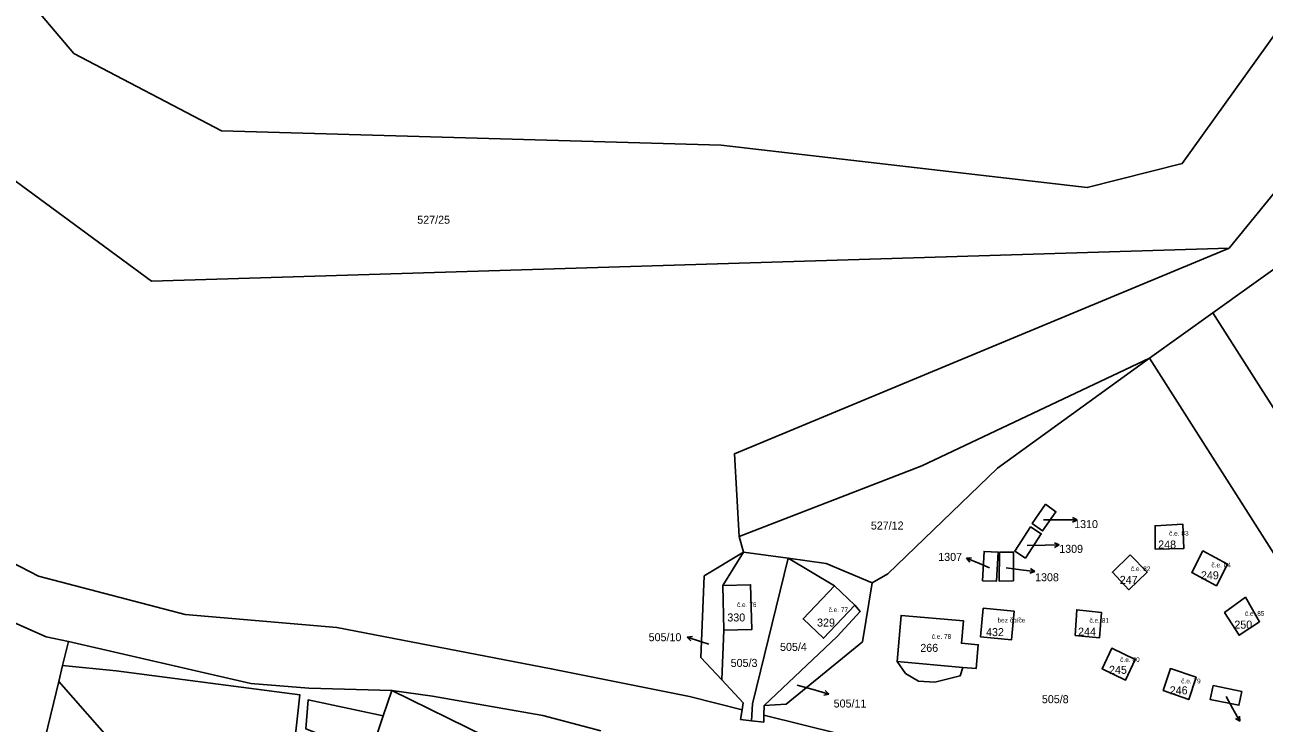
# Model space of a CAD drawing. Extents: x -887272 to -880188, y -1026687 to -1021896.
# Drawn here: x -883908.9 to -883645.6, y -1024025.9 to -1023877.6 of the extents above; entities that cross this region are included whole.
import ezdxf

# ---------------------------------------------------------------- set-up
doc = ezdxf.new("R2010")
doc.units = 0
for name, color, linetype in [('Definiční body', 7, 'Continuous'), ('Hranice parcel', 7, 'Continuous'), ('Parcelní čísla', 7, 'Continuous'), ('Polygon budovy', 7, 'Continuous'), ('Pop  PČ popisy', 7, 'Continuous'), ('Vnitřní kresba', 7, 'Continuous')]:
    doc.layers.add(name, color=color, linetype=linetype)

msp = doc.modelspace()

# ---------------------------------------------------------------- linework, layer by layer
at = {"layer": 'Hranice parcel'}
for p, q in [((-883618.89, -1023883.14), (-883653, -1023925)), ((-883656.45, -1023938.75), (-883630.8, -1023920.38)), ((-883656.45, -1023938.75), (-883669.93, -1023948.4)), ((-883590.41, -1024042.65), (-883656.45, -1023938.75)), ((-883608.39, -1024045.1), (-883669.93, -1023948.4)), ((-883757.1, -1023986.22), (-883756.18, -1023989.56)), ((-883756.18, -1023989.56), (-883760.62, -1023996.66)), ((-883746.68, -1023990.84), (-883756.18, -1023989.56)), ((-883736.89, -1023996.69), (-883746.68, -1023990.84)), ((-883760.62, -1023996.66), (-883760.36, -1024006.16)), ((-883732.53, -1024000.81), (-883736.89, -1023996.69)), ((-883705.25, -1024001.45), (-883705.83, -1024007.56)), ((-883760.36, -1024006.16), (-883760.82, -1024016.71)), ((-883899.62, -1024008.57), (-883900.86, -1024013.67)), ((-883900.86, -1024013.67), (-883901.68, -1024017.03)), ((-883904.58, -1024028.99), (-883901.68, -1024017.03)), ((-883751.78, -1024022.1), (-883751.85, -1024024.16)), ((-883832.76, -1024024.32), (-883835.54, -1024032.54))]:
    msp.add_line(p, q, dxfattribs=at)
for points in [[(-883756.5, -1024023.04), (-883767.66, -1024020.24), (-883797.06, -1024014.34), (-883842.62, -1024005.56), (-883874.8, -1024002.84), (-883906.02, -1023994.68), (-883929.04, -1023982.78), (-884005.12, -1023932.5), (-884033.98, -1023912.56), (-884080.28, -1023877.34), (-884136.58, -1023830.48), (-884162.3, -1023804.42), (-884180.14, -1023781.6), (-884204.86, -1023736.02), (-884224.62, -1023704.92), (-884247.24, -1023674.52), (-884253.66, -1023666.34), (-884254.22, -1023665.64)], [(-883940.39, -1023824.94), (-883938.55, -1023836.46), (-883898.48, -1023883.66), (-883867.13, -1023900.11), (-883760.97, -1023903.17), (-883683.16, -1023912.16), (-883662.96, -1023907.05), (-883633.66, -1023866.14)], [(-883979.65, -1023860.19), (-883882, -1023932), (-883653, -1023925)], [(-883653, -1023925), (-883758.14, -1023968.71), (-883757.1, -1023986.22)], [(-883757.1, -1023986.22), (-883718.33, -1023971.26), (-883669.93, -1023948.4)], [(-883669.93, -1023948.4), (-883702.2, -1023971.74), (-883725.5, -1023994.16), (-883728.86, -1023996.08)], [(-883692.06, -1023979.41), (-883689.83, -1023980.99), (-883692.66, -1023985.08), (-883694.85, -1023983.5), (-883692.06, -1023979.41)], [(-883696.29, -1023990.83), (-883698.57, -1023989.35), (-883695.21, -1023984.2), (-883692.94, -1023985.66), (-883696.29, -1023990.83)], [(-883668.72, -1023988.96), (-883662.66, -1023988.8), (-883662.82, -1023983.66), (-883668.76, -1023983.98), (-883668.72, -1023988.96)], [(-883756.18, -1023989.56), (-883764.52, -1023994.6), (-883765.26, -1024011.96), (-883760.82, -1024016.71)], [(-883705.41, -1023995.64), (-883705.06, -1023989.43), (-883702.05, -1023989.57), (-883702.41, -1023995.71), (-883705.41, -1023995.64)], [(-883698.81, -1023995.68), (-883701.86, -1023995.72), (-883701.8, -1023989.58), (-883698.81, -1023989.56), (-883698.81, -1023995.68)], [(-883674.06, -1023990.16), (-883677.82, -1023993.84), (-883674.3, -1023997.54), (-883670.42, -1023993.82), (-883674.06, -1023990.16)], [(-883660.94, -1023993.92), (-883655.72, -1023996.7), (-883653.38, -1023992.12), (-883658.58, -1023989.3), (-883660.94, -1023993.92)], [(-883754.5, -1024025.36), (-883754.29, -1024021.81), (-883746.68, -1023990.84)], [(-883746.68, -1023990.84), (-883738.64, -1023991.96), (-883728.86, -1023996.08)], [(-883760.36, -1024006.16), (-883754.46, -1024006), (-883754.7, -1023996.5), (-883760.62, -1023996.66)], [(-883728.86, -1023996.08), (-883730.9, -1024008.58), (-883747.14, -1024021.86), (-883751.78, -1024022.1)], [(-883736.89, -1023996.69), (-883743.54, -1024003.74), (-883739.18, -1024007.85), (-883732.53, -1024000.81)], [(-883751.78, -1024022.1), (-883736.3, -1024007.5), (-883731.4, -1024002.14), (-883732.53, -1024000.81)], [(-883646.54, -1024004.34), (-883649.54, -1023999.13), (-883653.96, -1024002.38), (-883650.88, -1024007.22), (-883646.54, -1024004.34)], [(-883913.13, -1024003.65), (-883904.38, -1024007.55), (-883899.62, -1024008.57)], [(-883706.76, -1024014.3), (-883706.31, -1024009.22), (-883709.9, -1024008.9), (-883709.48, -1024004.13), (-883722.73, -1024003.02), (-883723.54, -1024012.82)], [(-883705.83, -1024007.56), (-883699.25, -1024008.18), (-883698.7, -1024002.1), (-883705.25, -1024001.45)], [(-883680.54, -1024007.74), (-883680.16, -1024002.36), (-883685.4, -1024001.8), (-883685.72, -1024007.26), (-883680.54, -1024007.74)], [(-883899.62, -1024008.57), (-883860.9, -1024017.44), (-883848.52, -1024018.46), (-883830.95, -1024018.96), (-883822.3, -1024020.14), (-883798.84, -1024024.24), (-883786.49, -1024027.54)], [(-883675.06, -1024016.78), (-883672.96, -1024012.34), (-883677.96, -1024009.96), (-883680, -1024014.34), (-883675.06, -1024016.78)], [(-883867.76, -1024045.3), (-883853.82, -1024050.22), (-883850.5, -1024019.86), (-883889.5, -1024014.8), (-883900.86, -1024013.67)], [(-883723.54, -1024012.82), (-883721.76, -1024015.36), (-883719, -1024016.96), (-883715.56, -1024017.2), (-883710.18, -1024015.86), (-883709.57, -1024014.05), (-883706.76, -1024014.3)], [(-883661.58, -1024020.86), (-883660.02, -1024016.12), (-883665.48, -1024014.3), (-883667.02, -1024018.94), (-883661.58, -1024020.86)], [(-883901.68, -1024017.03), (-883886.96, -1024033.84), (-883874.14, -1024042.96), (-883867.76, -1024045.3)], [(-883760.82, -1024016.71), (-883756.28, -1024021.58), (-883756.5, -1024023.04)], [(-883835.54, -1024032.54), (-883818.36, -1024041.34), (-883811, -1024028.73), (-883830.95, -1024018.96), (-883832.76, -1024024.32)], [(-883650.34, -1024019.14), (-883650.92, -1024022.08), (-883657.05, -1024020.84), (-883656.37, -1024017.92), (-883650.34, -1024019.14)], [(-883832.76, -1024024.32), (-883848.72, -1024020.95), (-883849.18, -1024027.12), (-883835.54, -1024032.54)], [(-883756.5, -1024023.04), (-883756.81, -1024025.08), (-883754.5, -1024025.36)], [(-883751.85, -1024024.16), (-883751.9, -1024025.67), (-883754.5, -1024025.36)], [(-883751.85, -1024024.16), (-883686.7, -1024040.32), (-883639.5, -1024046.16), (-883608.39, -1024045.1)]]:
    msp.add_lwpolyline(points, dxfattribs=at)
at = {"layer": 'Polygon budovy'}
for points in [[(-883668.76, -1023983.98), (-883668.72, -1023988.96), (-883662.66, -1023988.8), (-883662.82, -1023983.66)], [(-883674.06, -1023990.16), (-883677.82, -1023993.84), (-883674.3, -1023997.54), (-883670.42, -1023993.82)], [(-883658.58, -1023989.3), (-883660.94, -1023993.92), (-883655.72, -1023996.7), (-883653.38, -1023992.12)], [(-883760.36, -1024006.16), (-883754.46, -1024006), (-883754.7, -1023996.5), (-883760.62, -1023996.66)], [(-883743.54, -1024003.74), (-883739.18, -1024007.85), (-883732.53, -1024000.81), (-883736.89, -1023996.69)], [(-883653.96, -1024002.38), (-883650.88, -1024007.22), (-883646.54, -1024004.34), (-883649.54, -1023999.13)], [(-883722.73, -1024003.02), (-883723.54, -1024012.82), (-883709.57, -1024014.05), (-883706.76, -1024014.3), (-883706.31, -1024009.22), (-883709.9, -1024008.9), (-883709.48, -1024004.13)], [(-883705.25, -1024001.45), (-883705.83, -1024007.56), (-883699.25, -1024008.18), (-883698.7, -1024002.1)], [(-883685.4, -1024001.8), (-883685.72, -1024007.26), (-883680.54, -1024007.74), (-883680.16, -1024002.36)], [(-883672.96, -1024012.34), (-883677.96, -1024009.96), (-883680, -1024014.34), (-883675.06, -1024016.78)], [(-883665.48, -1024014.3), (-883667.02, -1024018.94), (-883661.58, -1024020.86), (-883660.02, -1024016.12)]]:
    msp.add_lwpolyline(points, close=True, dxfattribs=at)
at = {"layer": 'Pop  PČ popisy'}
for p, q in [((-883692.48, -1023982.69), (-883688.29, -1023982.71)), ((-883688.29, -1023982.71), (-883685.29, -1023982.71)), ((-883685.29, -1023982.71), (-883686.29, -1023982.21)), ((-883685.29, -1023982.71), (-883686.29, -1023983.21)), ((-883692.1, -1023988.1), (-883689.1, -1023988.05)), ((-883689.1, -1023988.05), (-883690.11, -1023987.56)), ((-883689.1, -1023988.05), (-883690.09, -1023988.57)), ((-883695.94, -1023988.16), (-883692.1, -1023988.1)), ((-883708.83, -1023990.87), (-883707.72, -1023990.78)), ((-883706.05, -1023991.99), (-883708.83, -1023990.87)), ((-883708.83, -1023990.87), (-883708.09, -1023991.71)), ((-883703.9, -1023992.87), (-883706.05, -1023991.99)), ((-883700.37, -1023992.93), (-883697.25, -1023993.3)), ((-883697.25, -1023993.3), (-883694.27, -1023993.67)), ((-883694.27, -1023993.67), (-883695.2, -1023993.05)), ((-883694.27, -1023993.67), (-883695.33, -1023994.04)), ((-883768.15, -1024007.63), (-883767.05, -1024007.47)), ((-883765.3, -1024008.56), (-883768.15, -1024007.63)), ((-883768.15, -1024007.63), (-883767.36, -1024008.42)), ((-883763.59, -1024009.12), (-883765.3, -1024008.56)), ((-883744.78, -1024017.82), (-883740.93, -1024018.9)), ((-883740.93, -1024018.9), (-883738.05, -1024019.73)), ((-883738.05, -1024019.73), (-883738.87, -1024018.97)), ((-883738.05, -1024019.73), (-883739.15, -1024019.93)), ((-883653.67, -1024020.23), (-883652.2, -1024022.87)), ((-883652.2, -1024022.87), (-883650.74, -1024025.49)), ((-883650.74, -1024025.49), (-883651.67, -1024024.86)), ((-883650.74, -1024025.49), (-883650.79, -1024024.38))]:
    msp.add_line(p, q, dxfattribs=at)
at = {"layer": 'Vnitřní kresba'}
msp.add_line((-883723.54, -1024012.82), (-883709.57, -1024014.05), dxfattribs=at)

# ---------------------------------------------------------------- texts
at = {"layer": 'Definiční body'}
for s, p in [('č.e. 83', (-883665.77, -1023986.07)), ('č.e. 82', (-883673.88, -1023993.59)), ('č.e. 84', (-883656.77, -1023992.8)), ('č.e. 76', (-883757.59, -1024001.23)), ('č.e. 77', (-883738.12, -1024002.3)), ('bez čp/če', (-883702.22, -1024004.5)), ('č.e. 81', (-883682.68, -1024004.57)), ('č.e. 85', (-883649.65, -1024003.09)), ('č.e. 78', (-883716.21, -1024007.98)), ('č.e. 80', (-883676.16, -1024012.88)), ('č.e. 79', (-883663.2, -1024017.43))]:
    msp.add_text(s, height=1, dxfattribs=at).set_placement(p)
at = {"layer": 'Parcelní čísla'}
for s, p in [('527/25', (-883825.51, -1023919.84)), ('1310', (-883685.94, -1023984.46)), ('527/12', (-883729.14, -1023984.77)), ('1309', (-883689.11, -1023989.72)), ('248', (-883668.08, -1023988.8)), ('1307', (-883714.82, -1023991.43)), ('1308', (-883694.24, -1023995.75)), ('247', (-883676.24, -1023996.31)), ('249', (-883659, -1023995.33)), ('330', (-883759.63, -1024004.29)), ('329', (-883740.56, -1024005.37)), ('432', (-883704.66, -1024007.4)), ('244', (-883685.1, -1024007.3)), ('250', (-883651.9, -1024005.81)), ('505/10', (-883776.35, -1024008.48)), ('505/4', (-883748.43, -1024010.54)), ('266', (-883718.63, -1024010.75)), ('505/3', (-883758.92, -1024013.94)), ('245', (-883678.53, -1024015.41)), ('246', (-883665.62, -1024019.76)), ('505/11', (-883737.04, -1024022.56)), ('505/8', (-883692.8, -1024021.64))]:
    msp.add_text(s, height=1.7, dxfattribs=at).set_placement(p)

doc.saveas('drawing.dxf')
